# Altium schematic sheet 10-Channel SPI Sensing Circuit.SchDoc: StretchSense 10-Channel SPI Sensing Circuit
size A3; Revision: 1.0; PageSetup: Record=PageOptions¦CenterHorizontal=True¦CenterVertical=True¦PrintScale=0.71¦XCorrection=1.00¦YCorrection=1.00¦PrintKind=0¦BorderSize=5000000¦LeftOffset=0¦BottomOffset=0¦Orientation=2¦PaperLength=1000¦PaperWidth=1000¦Scale=100¦PaperSource=7¦PrintQuality=600¦MediaType=1¦DitherType=10¦PaperKind=A4¦PrintScaleMode=1
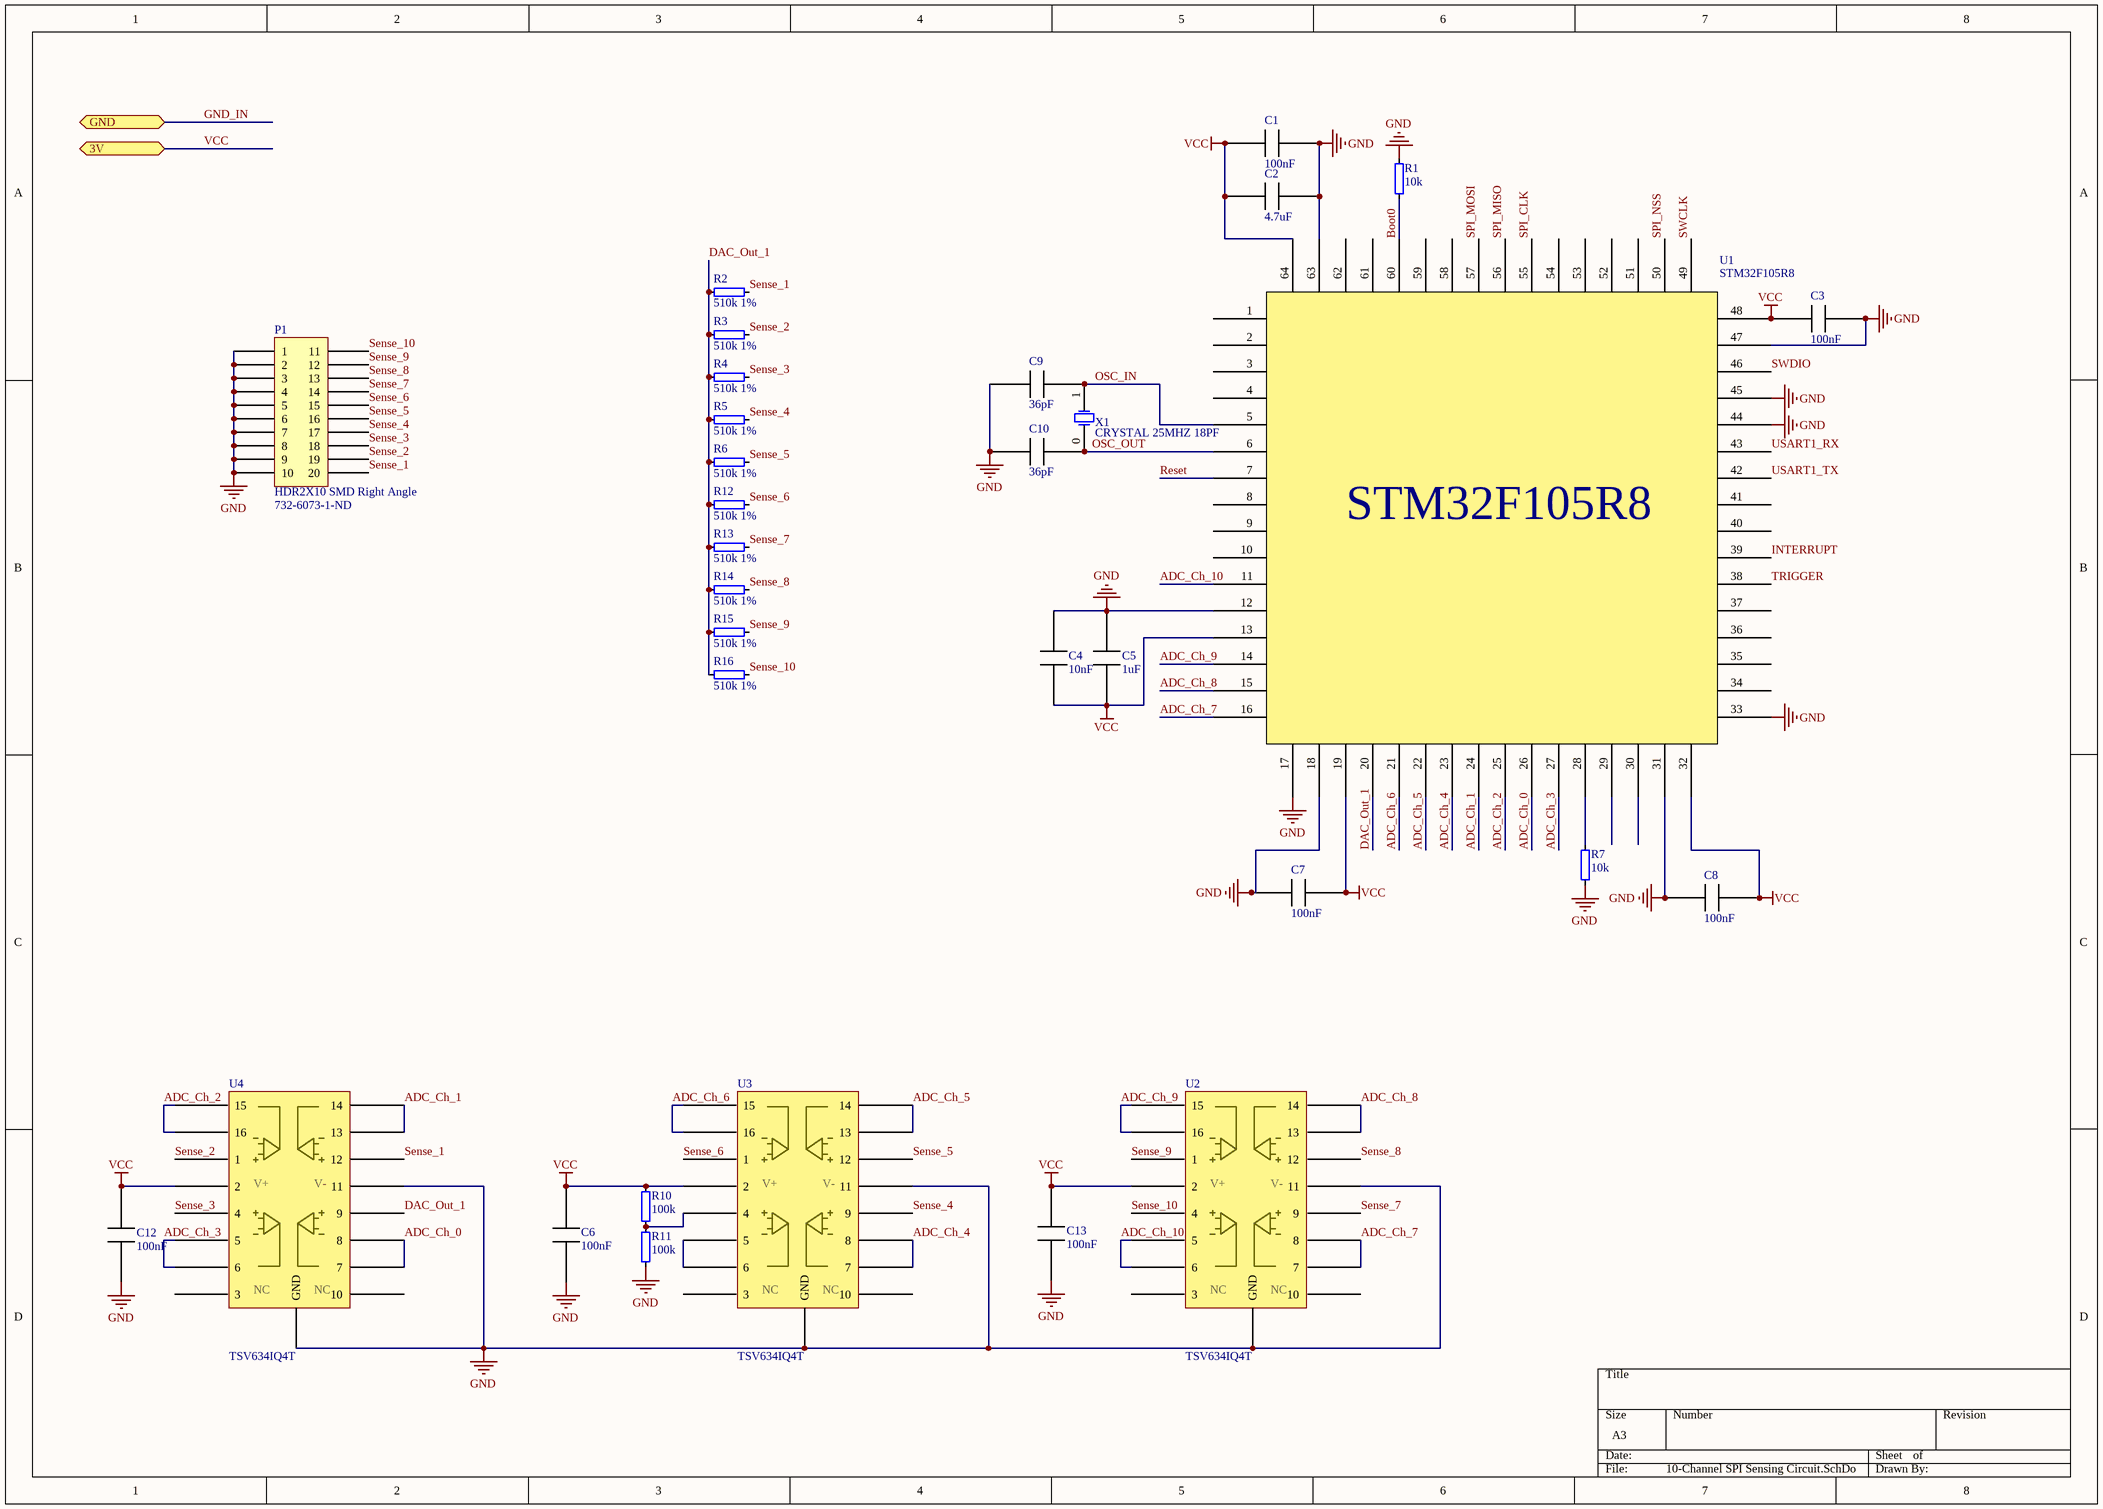
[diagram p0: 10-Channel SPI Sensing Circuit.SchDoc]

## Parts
C1  100nF  [0402 Cap]
C2  4.7uF  [0402 Cap]
C3  100nF  [0402 Cap]
C4  10nF  [0402 Cap]
C5  1uF  [0402 Cap]
C6  100nF  [0402 Cap]
C7  100nF  [0402 Cap]
C8  100nF  [0402 Cap]
C9  36pF  [0402 Cap]
C10  36pF  [0402 Cap]
C12  100nF  [0402 Cap]
C13  100nF  [0402 Cap]
P1  HDR2X10 SMD Right Angle  Supplier Part Number 1: 732-6073-1-ND  [HDR2X10 SMD RIGHT]
R1  10k  [0402 Res]
R2  510k 1%  [0402 Res]
R3  510k 1%  [0402 Res]
R4  510k 1%  [0402 Res]
R5  510k 1%  [0402 Res]
R6  510k 1%  [0402 Res]
R7  10k  [0402 Res]
R10  100k  [0402 Res]
R11  100k  [0402 Res]
R12  510k 1%  [0402 Res]
R13  510k 1%  [0402 Res]
R14  510k 1%  [0402 Res]
R15  510k 1%  [0402 Res]
R16  510k 1%  [0402 Res]
U1  STM32F105R8  [STM32F105R8]
U2  TSV634IQ4T  [QFN-16]
U3  TSV634IQ4T  [QFN-16]
U4  TSV634IQ4T  [QFN-16]
X1  CRYSTAL 25MHZ 18PF  [CRYSTAL 24MHZ 18PF SMD]

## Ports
3V, GND

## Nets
GND: C1.2 C2.2 C3.2 C4.2 C5.1 C6.1 C7.1 C8.1 C9.2 C10.2 C12.1 C13.1 P1.1 P1.2 P1.3 P1.4 P1.5 P1.6 P1.7 P1.8 P1.9 P1.10 R1.1 R7.2 R11.1 U1.12(Pin12) U1.17(Pin17) U1.18(Pin18) U1.31(Pin31) U1.33(Pin33) U1.44(Pin44) U1.45(Pin45) U1.47(Pin47) U1.63(Pin63) U2.11 U2.17(GND) U3.11 U3.17(GND) U4.11 U4.17(GND)
VCC: C1.1 C2.1 C3.1 C4.1 C5.2 C6.2 C7.2 C8.2 C12.2 C13.2 R10.2 U1.13(Pin13) U1.19(Pin19) U1.32(Pin32) U1.48(Pin48) U1.64(Pin64) U2.2 U3.2 U4.2 ; port 3V
ADC_Ch_0: U1.26(Pin26) U4.7 U4.8
ADC_Ch_1: U1.24(Pin24) U4.13 U4.14
ADC_Ch_2: U1.25(Pin25) U4.15 U4.16
ADC_Ch_3: U1.27(Pin27) U4.5 U4.6
ADC_Ch_4: U1.23(Pin23) U3.7 U3.8
ADC_Ch_5: U1.22(Pin22) U3.13 U3.14
ADC_Ch_6: U1.21(Pin21) U3.15 U3.16
ADC_Ch_7: U1.16(Pin16) U2.7 U2.8
ADC_Ch_8: U1.15(Pin15) U2.13 U2.14
ADC_Ch_9: U1.14(Pin14) U2.15 U2.16
ADC_Ch_10: U1.11(Pin11) U2.5 U2.6
Boot0: R1.2 U1.60(Pin60)
DAC_Out_1: R2.2 R3.2 R4.2 R5.2 R6.2 R12.1 R13.1 R14.1 R15.1 R16.1 U1.20(Pin20) U4.9
INTERRUPT: U1.39(Pin39)
OSC_IN: C9.1 U1.5(Pin5) X1.1(OSC_IN)
OSC_OUT: C10.1 U1.6(Pin6) X1.0
Reset: U1.7(Pin7)
Sense_1: P1.20 R2.1 U4.12
Sense_2: P1.19 R3.1 U4.1
Sense_3: P1.18 R4.1 U4.4
Sense_4: P1.17 R5.1 U3.9
Sense_5: P1.16 R6.1 U3.12
Sense_6: P1.15 R12.2 U3.1
Sense_7: P1.14 R13.2 U2.9
Sense_8: P1.13 R14.2 U2.12
Sense_9: P1.12 R15.2 U2.1
Sense_10: P1.11 R16.2 U2.4
SPI_CLK: U1.55(Pin55)
SPI_MISO: U1.56(Pin56)
SPI_MOSI: U1.57(Pin57)
SPI_NSS: U1.50(Pin50)
SWCLK: U1.49(Pin49)
SWDIO: U1.46(Pin46)
TRIGGER: U1.38(Pin38)
USART1_RX: U1.43(Pin43)
USART1_TX: U1.42(Pin42)
NetR7_1: R7.1 U1.28(Pin28)
NetR10_1: R10.1 R11.2 U3.4
NetU3_5: U3.5 U3.6

Not connected (* = marked no-connect by the designer): U1 1(Pin1) 2(Pin2) 3(Pin3) 4(Pin4) 8(Pin8) 9(Pin9) 10(Pin10) 29(Pin29) 30(Pin30) 34(Pin34) 35(Pin35) 36(Pin36) 37(Pin37) 40(Pin40) 41(Pin41) 51(Pin51) 52(Pin52) 53(Pin53) 54(Pin54) 58(Pin58) 59(Pin59) 61(Pin61) 62(Pin62); U2 3 10; U3 3 10; U4 3 10

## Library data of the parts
C1 C3 C6-C8 C12 C13 = Cap 0402 100nF 10%: Capacitor; Manufacturer: Samsung Electro-Mechanics America, Inc.; Manufacturer Part Number: CL05B104KO5NNNC; Capacitance: 0.1µF; Tolerance: ±10%; Voltage - Rated: 16V; Temperature Coefficient: X7R
C2 = Cap 0402 4.7uF 10%: Capacitor; Manufacturer: TDK Corporation; Manufacturer Part Number: C1005X5R1A475K050BC; Capacitance: 4.7µF; Tolerance: ±10%; Voltage - Rated: 10V; Temperature Coefficient: X5R
C4 = Cap 0402 10nF 10%: Capacitor; Manufacturer: Samsung Electro-Mechanics America, Inc.; Manufacturer Part Number: CL05B103KA5NNNC; Capacitance: 10000pF; Tolerance: ±10%; Voltage - Rated: 25V; Temperature Coefficient: X7R
C5 = Cap 0402 1uF 5%: Capacitor; Manufacturer: Samsung Electro-Mechanics America, Inc.; Manufacturer Part Number: CL05A105JQ5NNNC; Capacitance: 1µF; Tolerance: ±5%; Voltage - Rated: 6.3V; Temperature Coefficient: X5R
C9 C10 = Cap 36pF 0402: Capacitor; Manufacturer: Samsung Electro-Mechanics America, Inc.; Manufacturer Part Number: CL05C360JB5NNNC; Tolerance: ±5%; Voltage - Rated: 50V; Temperature Coefficient: C0G, NP0
P1 = Header 2x10 SMD R/A 2.54mm: Header; Manufacturer: Wurth Electronics Inc; Manufacturer Part Number: 610120249121; Connector Type: Header, Unshrouded; Number of Positions: 20; Number of Positions Loaded: All; Pitch: 0.100" (2.54mm)
R1 R7 = Res 0402 10k 5%: Resistor; Manufacturer: Yageo; Manufacturer Part Number: RC0402JR-0710KL; Tolerance: ±5%; Power (Watts): 0.063W, 1/16W; Temperature Coefficient: ±100ppm/°C
R2-R6 R12-R16 = Res 0402 510k 1%: Resistor; Manufacturer: Yageo; Manufacturer Part Number: RC0402FR-07510KL; Power (Watts): 0.063W, 1/16W; Temperature Coefficient: ±100ppm/°C
R10 R11 = Res 0402 100k 5%: Resistor; Manufacturer: Yageo; Manufacturer Part Number: RC0402FR-07100KL; Tolerance: ±1%; Power (Watts): 0.063W, 1/16W; Temperature Coefficient: ±100ppm/°C
U1 = STM32F105R8: Microcontroller; Part: ST Microelectronics STM32F105R8; Manufacturer: STMicroelectronics; Manufacturer Part Number: STM32F105R8T6; Core Processor: ARM® Cortex®-M3; Core Size: 32-Bit; Speed: 72MHz; Connectivity: CAN, I²C, IrDA, LIN, SPI, UART/USART, USB OTG; Peripherals: DMA, POR, PWM, Voltage Detect, WDT; Number of I/O: 51; Program Memory Size: 64KB (64K x 8); Program Memory Type: FLASH; RAM Size: 64K x 8; Voltage - Supply (Vcc/Vdd): 2 V ~ 3.6 V; Data Converters: A/D 16x12b; D/A 2x12b; Oscillator Type: Internal
U2-U4 = Quad Opamp TSV634IQ4T: Quad Opamp; Manufacturer: STMicroelectronics; Amplifier Type: General Purpose; Number of Circuits: 4; Output Type: Rail-to-Rail; Slew Rate: 0.34 V/µs; Gain Bandwidth Product: 880kHz; Current - Input Bias: 1pA; Voltage - Input Offset: 3mV; Current - Supply: 60µA; Current - Output / Channel: 74mA; Voltage - Supply, Single/Dual (±): 1.5 V ~ 5.5 V
X1 = CRYSTAL 25MHZ 18PF SMD: 445C25D24M00000; Manufacturer: CTS-Frequency Controls; Manufacturer Part Number: 445C25D25M00000; Frequency Stability: ±50ppm; Frequency Tolerance: ±20ppm; ESR (Equivalent Series Resistance): 40 Ohm; Operating Mode: Fundamental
